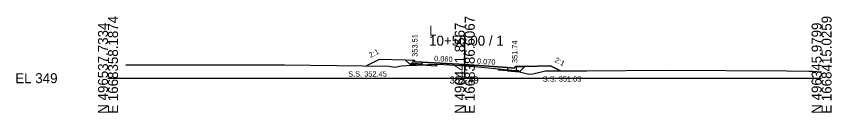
# Model space of a CAD drawing. Extents: x -26 to 203, y -10 to 5517.
# Drawn here: x -25.7 to 202.8, y 490.3 to 517.4 of the extents above; entities that cross this region are included whole.
import ezdxf

# ---------------------------------------------------------------- set-up
doc = ezdxf.new("R2010")
doc.units = 0
for name, color, linetype in [('Exist Cross Section Cell', 7, 'Continuous'), ('Exist XS Center Line Elevation Label', 7, 'Continuous'), ('Exist XS Ground Line', 7, 'Continuous'), ('Prop XS Earthwork Shape', 7, 'Continuous'), ('Prop XS Finish Grade', 7, 'Continuous'), ('Prop XS Finish Grade CurbGutter', 7, 'Continuous'), ('Prop XS Finish Grade Earthwork', 7, 'Continuous'), ('Prop XS Finish Grade Pavement', 7, 'Continuous'), ('Prop XS Geopak Shape', 7, 'Continuous'), ('Prop XS Hydro Elevations', 7, 'Continuous'), ('Prop XS Pvmt Edge Slope', 7, 'Continuous'), ('Prop XS SE Text', 7, 'Continuous'), ('Prop XS Side Slope Text', 7, 'Continuous'), ('Prop XS SS Elevation Text', 7, 'Continuous'), ('Prop XS Subgrade CurbGutter', 7, 'Continuous'), ('Prop XS Subgrade Earthwork', 7, 'Continuous')]:
    doc.layers.add(name, color=color, linetype=linetype)

msp = doc.modelspace()

# ---------------------------------------------------------------- linework, layer by layer
at = {"layer": 'Exist Cross Section Cell'}
for p, q in [((100, 500), (100, 511.92)), ((0, 500), (100, 500)), ((100, 500), (200, 500))]:
    msp.add_line(p, q, dxfattribs=at)
at = {"layer": 'Exist XS Ground Line'}
for p, q in [((4.96, 503.73), (45.48, 503.74)), ((45.48, 503.74), (47.19, 503.73)), ((47.19, 503.73), (49.51, 503.71)), ((49.51, 503.71), (78.81, 503.38)), ((78.81, 503.38), (80.43, 503.07)), ((80.43, 503.07), (82.27, 503.48)), ((82.27, 503.48), (85.23, 503.63)), ((85.23, 503.63), (92.06, 503.97)), ((92.06, 503.97), (94.09, 503.85)), ((94.09, 503.85), (100, 503.49)), ((100, 503.49), (100.68, 503.45)), ((100.68, 503.45), (102.76, 503.26)), ((102.76, 503.26), (109.49, 502.61)), ((109.49, 502.61), (111.89, 502.35)), ((111.89, 502.35), (113.95, 502.11)), ((113.95, 502.11), (114.96, 501.92)), ((114.96, 501.92), (117.99, 501.09)), ((117.99, 501.09), (119.12, 501.2)), ((119.12, 501.2), (122.65, 502.03)), ((122.65, 502.03), (134.23, 502.02)), ((134.23, 502.02), (156.2, 502.28)), ((156.2, 502.28), (190.23, 502.04)), ((190.23, 502.04), (196.4, 501.96)), ((196.4, 501.96), (197.44, 501.94)), ((197.44, 501.94), (200, 501.82))]:
    msp.add_line(p, q, dxfattribs=at)
at = {"layer": 'Prop XS Earthwork Shape'}
for points in [[(86.59, 503.7), (84.67, 503.81), (83.43, 505.05), (76, 505.21), (72.5, 503.45), (78.81, 503.38), (80.43, 503.07), (82.27, 503.48), (85.23, 503.63)], [(86.59, 503.7), (92.06, 503.97), (92.06, 503.37), (88, 503.61)], [(115.33, 501.81), (117.99, 501.09), (119.12, 501.2), (122.65, 502.03), (126.83, 502.03), (124, 503.44), (116.81, 503.29)], [(114.96, 501.92), (115.33, 501.81), (112, 502.04), (109.49, 502.22), (109.49, 502.61), (111.89, 502.35), (113.95, 502.11)]]:
    msp.add_lwpolyline(points, close=True, dxfattribs=at)
at = {"layer": 'Prop XS Finish Grade'}
for p, q in [((85.5, 505.01), (83.43, 505.05)), ((114.5, 503.24), (116.81, 503.29))]:
    msp.add_line(p, q, dxfattribs=at)
at = {"layer": 'Prop XS Finish Grade CurbGutter'}
for p, q in [((85.5, 505.01), (85.75, 505.01)), ((85.75, 505.01), (85.88, 504.97)), ((85.97, 504.87), (85.88, 504.97)), ((86.03, 504.62), (85.97, 504.87)), ((86.13, 504.53), (86.03, 504.62)), ((86.25, 504.51), (86.13, 504.53)), ((88, 504.53), (86.25, 504.51)), ((112, 502.96), (113.75, 502.77)), ((113.75, 502.77), (113.87, 502.79)), ((113.87, 502.79), (113.97, 502.88)), ((113.97, 502.88), (114.03, 503.13)), ((114.03, 503.13), (114.12, 503.22)), ((114.25, 503.24), (114.12, 503.22)), ((114.5, 503.24), (114.25, 503.24))]:
    msp.add_line(p, q, dxfattribs=at)
at = {"layer": 'Prop XS Finish Grade Earthwork'}
for p, q in [((76, 505.21), (72.5, 503.45)), ((83.43, 505.05), (76, 505.21)), ((116.81, 503.29), (124, 503.44)), ((124, 503.44), (126.83, 502.03))]:
    msp.add_line(p, q, dxfattribs=at)
at = {"layer": 'Prop XS Finish Grade Pavement'}
for p, q in [((88, 504.53), (100, 503.81)), ((100, 503.81), (112, 502.96))]:
    msp.add_line(p, q, dxfattribs=at)
at = {"layer": 'Prop XS Geopak Shape'}
msp.add_lwpolyline([(72.5, 503.45), (78.81, 503.38), (80.43, 503.07), (82.27, 503.48), (85.23, 503.63), (92.06, 503.97), (94.09, 503.85), (100, 503.49), (100.68, 503.45), (102.76, 503.26), (109.49, 502.61), (111.89, 502.35), (113.95, 502.11), (114.96, 501.92), (117.99, 501.09), (119.12, 501.2), (122.65, 502.03), (126.83, 502.03), (124, 503.44), (116.81, 503.29), (114.5, 503.24), (114.25, 503.24), (114.12, 503.22), (114.03, 503.13), (113.97, 502.88), (113.87, 502.79), (113.75, 502.77), (112, 502.96), (100, 503.81), (88, 504.53), (86.25, 504.51), (86.13, 504.53), (86.03, 504.62), (85.97, 504.87), (85.88, 504.97), (85.75, 505.01), (85.5, 505.01), (83.43, 505.05), (76, 505.21)], close=True, dxfattribs=at)
at = {"layer": 'Prop XS Pvmt Edge Slope'}
for p, q in [((85, 504.13), (84.67, 503.81)), ((85.5, 504.1), (85, 504.13)), ((114.5, 502.2), (115, 502.17)), ((115, 502.17), (115.33, 501.81))]:
    msp.add_line(p, q, dxfattribs=at)
at = {"layer": 'Prop XS Subgrade CurbGutter'}
for p, q in [((85.5, 504.1), (85.5, 505.01)), ((88, 503.95), (85.5, 504.1)), ((88, 504.53), (88, 503.95)), ((112, 502.96), (112, 502.38)), ((114.5, 502.2), (114.5, 503.24)), ((112, 502.38), (114.5, 502.2))]:
    msp.add_line(p, q, dxfattribs=at)
at = {"layer": 'Prop XS Subgrade Earthwork'}
for p, q in [((84.67, 503.81), (83.43, 505.05)), ((88, 503.61), (84.67, 503.81)), ((88, 503.61), (88, 503.61)), ((92.06, 503.37), (88, 503.61)), ((92.06, 503.37), (92.06, 503.97)), ((115.33, 501.81), (116.81, 503.29)), ((109.49, 502.22), (109.49, 502.61)), ((112, 502.04), (109.49, 502.22)), ((112, 502.04), (112, 502.05)), ((112, 502.05), (115.33, 501.81))]:
    msp.add_line(p, q, dxfattribs=at)

# ---------------------------------------------------------------- texts
at = {"layer": 'Exist Cross Section Cell'}
for s, p in [('E 1668358.1874', (2.8, 490)), ('E 1668386.6067', (102.8, 490)), ('E 1668415.0259', (202.8, 490)), ('N 496537.7334', (0, 490)), ('N 496441.8567', (100, 490)), ('N 496345.9799', (200, 490))]:
    msp.add_text(s, height=2.8, rotation=90, dxfattribs=at).set_placement(p)
for s, p in [('L', (90, 511.92)), ('10+50.00 / 1', (90, 509.12)), ('EL 349', (-26, 498.6))]:
    msp.add_text(s, height=2.8, dxfattribs=at).set_placement(p)
at = {"layer": 'Exist XS Center Line Elevation Label'}
msp.add_text('352.49', height=2, dxfattribs=at).set_placement((95.73, 498.49))
at = {"layer": 'Prop XS Hydro Elevations'}
for s, p in [('353.51', (86.75, 506.01)), ('351.74', (114.75, 504.24))]:
    msp.add_text(s, height=1.5, rotation=90, dxfattribs=at).set_placement(p)
at = {"layer": 'Prop XS SE Text'}
for s, rotation, p in [('0.060', 356.5664, (91.38, 504.82)), ('0.070', 355.9687, (103.38, 504.07))]:
    msp.add_text(s, height=1.5, rotation=rotation, dxfattribs=at).set_placement(p)
at = {"layer": 'Prop XS Side Slope Text'}
for rotation, p in [(26.5651, (73.58, 505.67)), (333.4349, (125.02, 504.61))]:
    msp.add_text('2:1', height=1.5, rotation=rotation, dxfattribs=at).set_placement(p)
at = {"layer": 'Prop XS SS Elevation Text'}
for s, p in [('S.S. 352.45', (67.33, 500.45)), ('S.S. 351.03', (121.85, 499.03))]:
    msp.add_text(s, height=1.5, dxfattribs=at).set_placement(p)

doc.saveas('drawing.dxf')
